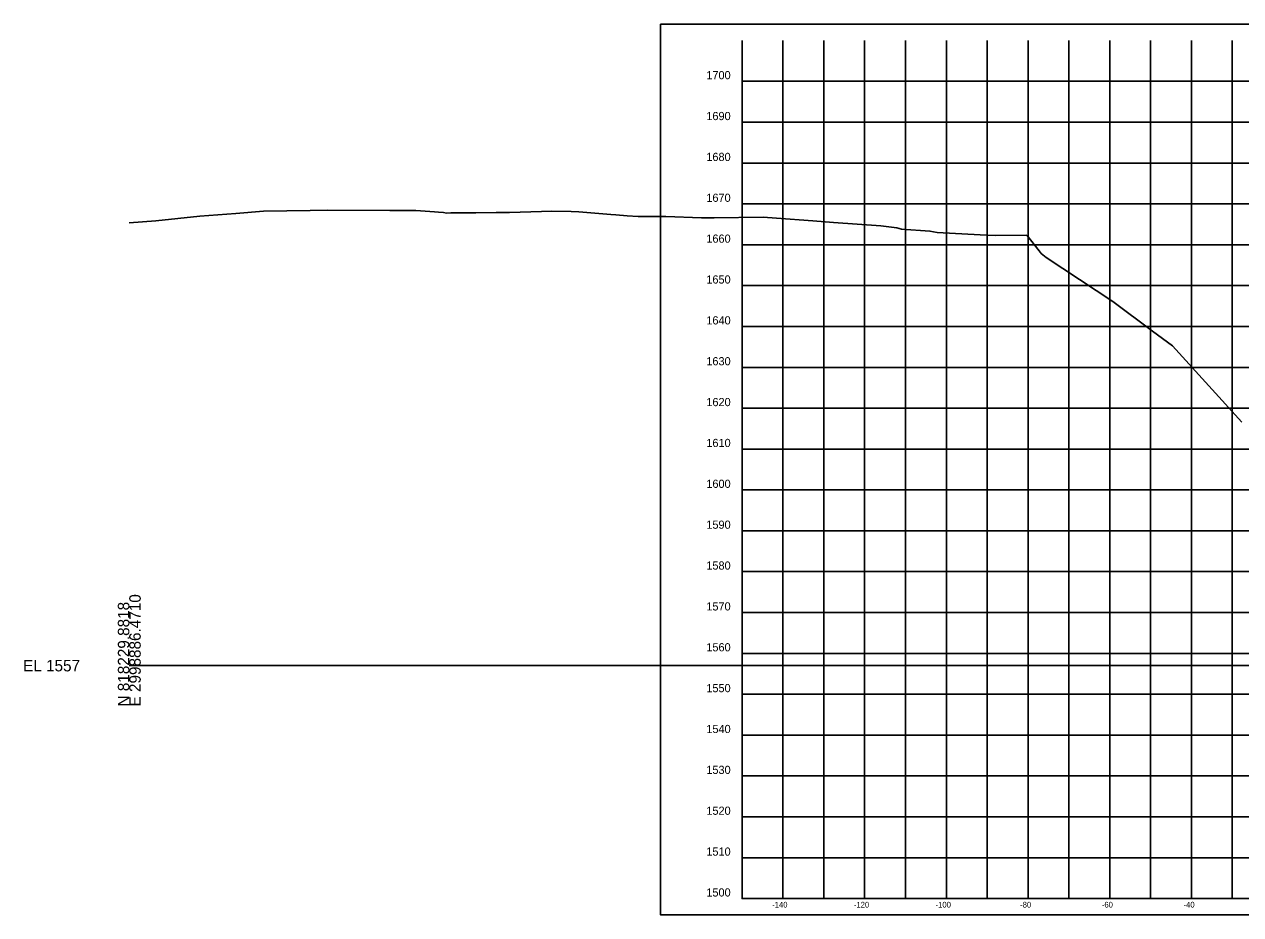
# Model space of a CAD drawing. Extents: x -26 to 1067, y -71 to 1837.
# Drawn here: x -25.7 to 272, y 1439.1 to 1656.9 of the extents above; entities that cross this region are included whole.
import ezdxf

# ---------------------------------------------------------------- set-up
doc = ezdxf.new("R2010")
doc.units = 0
for name, color, linetype in [('DESIGN - SHEET - Corner Text', 7, 'Continuous'), ('DESIGN - SHEET - Light Grid', 7, 'Continuous'), ('DESIGN - SHEET - Linework', 7, 'Continuous'), ('DESIGN - SHEET - Plot Shape', 7, 'Continuous'), ('SURVEY - GROUND - Top of Ground', 7, 'Continuous')]:
    doc.layers.add(name, color=color, linetype=linetype)

msp = doc.modelspace()

# ---------------------------------------------------------------- linework, layer by layer
at = {"layer": 'DESIGN - SHEET - Light Grid'}
msp.add_line((0, 1500), (300, 1500), dxfattribs=at)
at = {"layer": 'DESIGN - SHEET - Linework'}
for p, q in [((160, 1443), (160, 1653)), ((170, 1443), (170, 1653)), ((180, 1443), (180, 1653)), ((190, 1443), (190, 1653)), ((200, 1443), (200, 1653)), ((210, 1443), (210, 1653)), ((220, 1443), (220, 1653)), ((230, 1443), (230, 1653)), ((240, 1443), (240, 1653)), ((250, 1443), (250, 1653)), ((260, 1443), (260, 1653)), ((270, 1443), (270, 1653)), ((150, 1643), (450, 1643)), ((150, 1633), (450, 1633)), ((150, 1623), (450, 1623)), ((150, 1613), (450, 1613)), ((150, 1603), (450, 1603)), ((150, 1593), (450, 1593)), ((150, 1583), (450, 1583)), ((150, 1573), (450, 1573)), ((150, 1563), (450, 1563)), ((150, 1553), (450, 1553)), ((150, 1543), (450, 1543)), ((150, 1533), (450, 1533)), ((150, 1523), (450, 1523)), ((150, 1513), (450, 1513)), ((150, 1503), (450, 1503)), ((150, 1493), (450, 1493)), ((150, 1483), (450, 1483)), ((150, 1473), (450, 1473)), ((150, 1463), (450, 1463)), ((150, 1453), (450, 1453))]:
    msp.add_line(p, q, dxfattribs=at)
msp.add_lwpolyline([(150, 1653), (150, 1443), (450, 1443), (450, 1653)], dxfattribs=at)
at = {"layer": 'DESIGN - SHEET - Plot Shape'}
msp.add_lwpolyline([(130, 1656.94), (470, 1656.94), (470, 1439.06), (130, 1439.06)], close=True, dxfattribs=at)
at = {"layer": 'SURVEY - GROUND - Top of Ground'}
msp.add_lwpolyline([(0, 1608.4), (6.46, 1608.88), (17.27, 1610.03), (26.08, 1610.68), (32.89, 1611.23), (44.3, 1611.39), (48.64, 1611.49), (63.78, 1611.39), (70.14, 1611.37), (74.74, 1611.09), (75.69, 1610.97), (76.94, 1610.88), (77.65, 1610.76), (78.68, 1610.77), (84.86, 1610.83), (89.83, 1610.89), (93.07, 1610.88), (100.92, 1611.1), (103.35, 1611.19), (108.15, 1611.14), (110.07, 1611.06), (113.95, 1610.72), (117.9, 1610.39), (119.08, 1610.31), (121.91, 1610.05), (124.54, 1609.95), (131.37, 1609.92), (140.09, 1609.59), (141.47, 1609.6), (143.15, 1609.62), (155.2, 1609.77), (158.46, 1609.52), (167.29, 1608.86), (172.39, 1608.48), (183.95, 1607.66), (187.92, 1607.16), (189.05, 1606.8), (195.96, 1606.34), (197.77, 1605.97), (208.27, 1605.4), (212.03, 1605.25), (219.68, 1605.33), (222.75, 1601.53), (223.22, 1600.88), (224.41, 1599.9), (240.79, 1589.09), (250.43, 1581.84), (255.36, 1578.26), (272.31, 1559.58)], dxfattribs=at)

# ---------------------------------------------------------------- texts
at = {"layer": 'DESIGN - SHEET - Corner Text'}
for s, height, p in [('1700', 2, (141.25, 1643.5)), ('1690', 2, (141.25, 1633.5)), ('1680', 2, (141.25, 1623.5)), ('1670', 2, (141.25, 1613.5)), ('1660', 2, (141.25, 1603.5)), ('1650', 2, (141.25, 1593.5)), ('1640', 2, (141.25, 1583.5)), ('1630', 2, (141.25, 1573.5)), ('1620', 2, (141.25, 1563.5)), ('1610', 2, (141.25, 1553.5)), ('1600', 2, (141.25, 1543.5)), ('1590', 2, (141.25, 1533.5)), ('1580', 2, (141.25, 1523.5)), ('1570', 2, (141.25, 1513.5)), ('1560', 2, (141.25, 1503.5)), ('1550', 2, (141.25, 1493.5)), ('1540', 2, (141.25, 1483.5)), ('1530', 2, (141.25, 1473.5)), ('1520', 2, (141.25, 1463.5)), ('1510', 2, (141.25, 1453.5)), ('1500', 2, (141.25, 1443.5)), ('-140', 1.4, (157.37, 1440.8)), ('-120', 1.4, (177.37, 1440.8)), ('-100', 1.4, (197.37, 1440.8)), ('-80', 1.4, (218.06, 1440.8)), ('-60', 1.4, (238.06, 1440.8)), ('-40', 1.4, (258.06, 1440.8))]:
    msp.add_text(s, height=height, dxfattribs=at).set_placement(p)
at = {"layer": 'DESIGN - SHEET - Light Grid'}
for s, p in [('E 2998886.4710', (2.8, 1490)), ('N 818229.8818', (0, 1490))]:
    msp.add_text(s, height=2.8, rotation=90, dxfattribs=at).set_placement(p)
msp.add_text('EL 1557', height=2.8, dxfattribs=at).set_placement((-26, 1498.6))

doc.saveas('drawing.dxf')
